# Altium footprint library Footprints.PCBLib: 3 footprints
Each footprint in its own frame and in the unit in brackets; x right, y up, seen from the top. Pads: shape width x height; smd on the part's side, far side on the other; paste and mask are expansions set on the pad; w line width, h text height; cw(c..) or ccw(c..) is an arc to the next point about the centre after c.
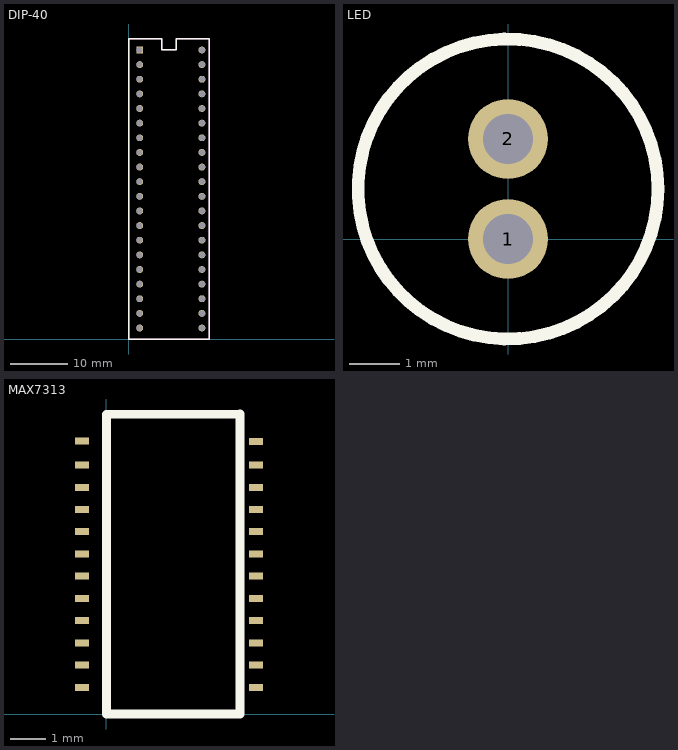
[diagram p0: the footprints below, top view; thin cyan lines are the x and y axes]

## DIP-40 [mm]
pads (40):
  rect 1.2x1.2 hole 1.041: 1(1.905,50.165)
  round 1.2 hole 1.041: 2(1.905,47.625) 3(1.905,45.085) 4(1.905,42.545) 5(1.905,40.005) 6(1.905,37.465) 7(1.905,34.925) 8(1.905,32.385) 9(1.905,29.845) 10(1.905,27.305) 11(1.905,24.765) 12(1.905,22.225) 13(1.905,19.685) 14(1.905,17.145) 15(1.905,14.605) 16(1.905,12.065) 17(1.905,9.525) 18(1.905,6.985) 19(1.905,4.445) 20(1.905,1.905) 21(12.7,1.905) 22(12.7,4.445) 23(12.7,6.985) 24(12.7,9.525) 25(12.7,12.065) 26(12.7,14.605) 27(12.7,17.145) 28(12.7,19.685) 29(12.7,22.225) 30(12.7,24.765) 31(12.7,27.305) 32(12.7,29.845) 33(12.7,32.385) 34(12.7,34.925) 35(12.7,37.465) 36(12.7,40.005) 37(12.7,42.545) 38(12.7,45.085) 39(12.7,47.625) 40(12.7,50.165)
Top Overlay:
  lines w0.254: 0,0 0,52.07 5.715,52.07 5.715,50.165 8.255,50.165 8.255,52.07 13.97,52.07 13.97,0 0,0
Mechanical 1:
  lines w0.254: 0,0 13.97,0 ; 0,0 13.97,0 ; 0,0 0,52.07 ; 0,0 0,52.07 ; 0,0 13.97,0 ; 0,52.07 5.715,52.07 ; 5.715,50.165 5.715,52.07 ; 5.715,50.165 8.255,50.165 8.255,52.07 13.97,52.07 ; 5.715,50.165 5.715,52.07 ; 13.97,0 13.97,52.07 ; 13.97,0 13.97,52.07

## LED [mm]
pads (2):
  round 1.6 hole 1: 1(0,0) 2(0,2)
Top Overlay:
  circle w0.254: c0,1 r3

## MAX7313 [mm]
pads (24):
  rect 0.41x0.2 smd: 1(-0.699,7.798) 2(-0.699,7.112) 3(-0.699,6.477) 4(-0.699,5.842) 5(-0.699,5.207) 6(-0.699,4.572) 7(-0.699,3.937) 8(-0.699,3.302) 9(-0.699,2.667) 10(-0.699,2.032) 11(-0.699,1.397) 12(-0.699,0.762) 13(4.27,0.762) 14(4.27,1.397) 15(4.27,2.032) 16(4.27,2.667) 17(4.27,3.302) 18(4.27,3.937) 19(4.27,4.572) 20(4.27,5.207) 21(4.27,5.842) 22(4.27,6.477) 23(4.27,7.112) 24(4.27,7.789)
Top Overlay:
  lines w0.254: 0,8.56 0,0 3.81,0 3.81,8.55 3.8,8.56 ; 0.01,8.56 3.81,8.57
